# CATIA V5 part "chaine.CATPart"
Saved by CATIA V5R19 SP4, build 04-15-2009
Part number: chaine
Bounding box of the stored display mesh (mm): x 0 to 6, y -123.064 to 568.53, z -107.861 to 137.64
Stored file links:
  G:\EU_thinkMotion\CFAO_2010\MMS_groupe1\MMS_groupe1\A reprendre\OK\rdeneffle\chaine.CATPart
  G:\EU_thinkMotion\CFAO_2010\MMS_groupe1\MMS_groupe1\A reprendre\OK\rdeneffle\piece haute carter.CATPart
  G:\EU_thinkMotion\CFAO_2010\MMS_groupe1\MMS_groupe1\A reprendre\OK\rdeneffle\piece carter entourant.CATPart
  G:\EU_thinkMotion\CFAO_2010\MMS_groupe1\MMS_groupe1\A reprendre\OK\rdeneffle\systeme d'ouverture de porte de voiture.CATProduct
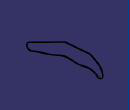
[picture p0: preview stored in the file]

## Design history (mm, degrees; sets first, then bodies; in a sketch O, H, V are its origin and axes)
Body1 (main body)
  Sketch1 on yz-plane, origin (0, 0, 0), H (0, 1, 0), V (0, 0, 1)
    line L1 (-106.1564, -49.2824) -> (223.2956, 118.5761)
    point P2 (223.2956, 118.5761)
    point P3 (-83.5387, -106.703)
    arc A1 centre (-92.083, -76.9038) radius 31 from (-106.1564, -49.2824) to (-83.5387, -106.703) ccw
    line L2 (223.2956, 118.5761) -> (447.4865, 137.6403)
    point P5 (447.4865, 137.6403)
    point P6 (420.2536, 7.0013)
    point P7 (537.5612, 20.2202)
    point P8 (505.8777, -64.5809)
    point P9 (547.6952, 49.517)
    spline S1 through (447.4865, 137.6403) (521.0029, 102.8505) (563.1412, 54.4305) (568.5297, 21.6172)
    arc A2 centre (537.5612, 20.2202) radius 31 from (511.2735, 3.7898) to (568.5297, 21.6172) ccw
    point P10 (511.2735, 3.7898)
    point P11 (568.5297, 21.6172)
    line L3 (-103.2926, -50.0679) -> (224.2036, 116.794)
    point P13 (224.2036, 116.794)
    point P14 (-81.9799, -104.1755)
    arc A3 centre (-92.083, -76.9038) radius 29.083 from (-103.2926, -50.0679) to (-81.9799, -104.1755) ccw
    point P15 (-92.083, -76.9038)
    line L4 (224.2036, 116.794) -> (447.9991, 135.8246)
    point P16 (224.2036, 116.794)
    point P17 (447.9991, 135.8246)
    spline S2 through (447.9991, 135.8246) (520.0805, 100.5635) (561.1526, 54.6439) (566.5369, 21.4478)
    arc A4 centre (537.5612, 20.2202) radius 29.0017 from (512.9448, 4.8862) to (566.5369, 21.4478) ccw
    point P18 (566.5369, 21.4478)
    point P19 (512.9448, 4.8862)
    spline S3 through (-81.9799, -104.1755) (30.616, -64.39) (125.3374, -33.0372) (256.9597, 9.0182) (360.9371, 6.8767) (402.606, 16.157) (512.9448, 4.8862)
    spline S4 through (-83.5387, -106.703) (30.616, -67.7682) (125.9755, -34.7608) (256.6036, 6.8766) (361.6493, 5.449) (433.6007, 18.6555) (461.3603, 19.0125) (511.2735, 3.7898)
    point P20 (447.4865, 137.6403)
    point P21 (568.5297, 21.6172)
    point P22 (447.9991, 135.8246)
    point P23 (566.5369, 21.4478)
    point P24 (563.1412, 54.4305)
    point P25 (561.1526, 54.6439)
    point P26 (-81.9799, -104.1755)
    point P28 (512.9448, 4.8862)
    point P29 (-83.5387, -106.703)
    point P30 (511.2735, 3.7898)
    radius A1 = 31
    length L1 = 369.75
    length L2 = 225
    distance P6 P7 = 118.05
    radius A2 = 31
    distance L3 L1 = 2
    distance P21 P23 = 2
    distance P24 P25 = 2
    distance P13 P2 = 2
    distance P7 P15 = 637.091
    tangency: A1 L1
    coincidence: P20 P5, A2 P9, P21 P11, P16 P13, P22 P17, P23 P18, P26 P14, P28 P19, P29 P3, P30 P10
    parallelism: L4 L2
    concentricity: A3 A1, A4 A2
  Pad1: profile Sketch1, direction (1, 0, 0), length 6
